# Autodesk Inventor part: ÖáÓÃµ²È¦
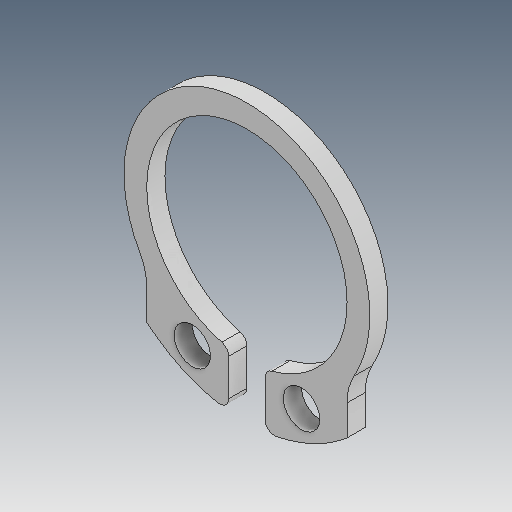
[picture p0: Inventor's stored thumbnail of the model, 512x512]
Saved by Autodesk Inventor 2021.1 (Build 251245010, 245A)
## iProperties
Created: 2019-04
Part Number: ÖáÓÃµ²È¦
Material: Ogólny
Document SubType Name: Modeling
Designer: user
Density: 1 g/cm^3
Appearance: Domyślna
Author: user
Revision Number: ÈÎºÎ
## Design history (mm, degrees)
feature "ÊäÈë1"
node "Bryła1"
